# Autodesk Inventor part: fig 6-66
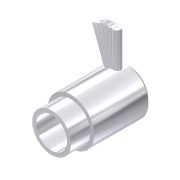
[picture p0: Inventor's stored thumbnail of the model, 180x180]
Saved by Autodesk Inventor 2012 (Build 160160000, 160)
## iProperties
Shininess: 77.0
Angle Display Precision: 2
Document Length Units: 11269
Document Angle Units: 11279
Document Time Units: 11290
Document Mass Units: 11283
Document Length Units Precision: 3
Document Angle Units Precision: 2
Compacted: True
Created: 2001-12
Part Number: fig 6-66
Document SubType Name: Modeling
Designer: Renu Muthoo
Density: 1 g/cm^3
Material: Default
Density: 0.0
Volumn: 0.0
Area: 0.0
PropertySet Name: Model Information
Control State: 0
Master: False
Checked Out: False
Author: Renu Muthoo
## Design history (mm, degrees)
sketch "Sketch2"
  geometry: L1 (-9.573, -4.327)-(-9.573, -5.327); L2 (-9.573, -5.327)-(-4.573, -5.327); L3 (-4.573, -5.327)-(-4.573, -6.327); L4 (-4.573, -6.327)-(9.427, -6.327); L5 (9.427, -6.327)-(10.427, -5.327); L6 (10.427, -5.327)-(10.427, -4.327); L7 (10.427, -4.327)-(-9.573, -4.327); L8 (-13.687, -0.327)-(14, -0.327)
  constraints: 16 end point, 5 parallel, 1 perpendicular, 1 vertical
  dimensions: "d9" = 20 distance of L6.end L1.start; "d10" = 5 distance of L1.end L2.end; "d11" = 12 diameter of L4 L8; "d12" = 10 diameter of L2 L8; "d13" = 8 diameter of L7 L8; "d14" = 45 deg angle of L5 L4; "d15" = 1 horizontal distance of L5.end L4.end
revolve "Revolution2" sketch "Sketch2" stored, may be unused: angle "d16" = 90 deg
workplane "Work Plane1"
workplane "Work Plane2"
sketch "Sketch3"
  geometry: L1 (-4, 8)-(4, 8) reference; C1 r 1 at (-0.098, 5)
  constraints: 1 centre point
  dimensions: "d18" = 3 distance from line of L1 C1.centre; "d19" = 2 diameter of C1
extrude "Extrusion1" join sketch "Sketch3" distance "d20" = 10; taper "d21" = 0 deg
pattern_circular "Circular Pattern3" dims angle "d29" = 20 deg
body "Solid1"
other parameters: "d17" = -1
